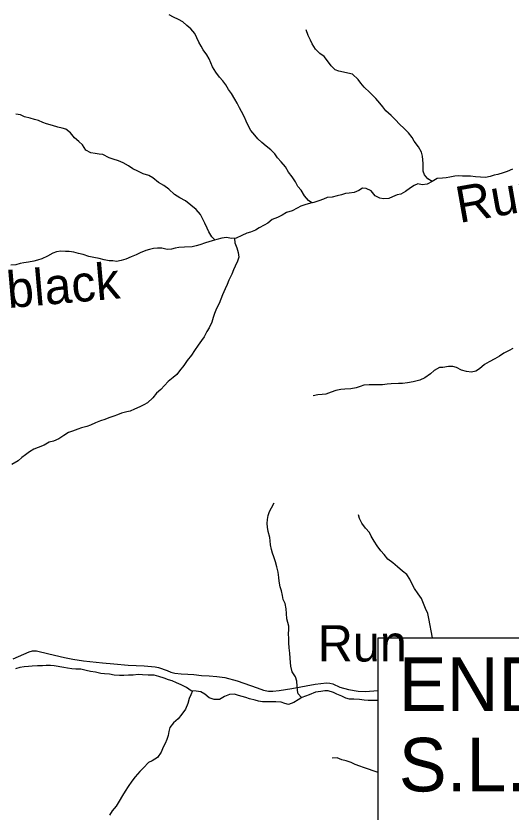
# Model space of a CAD drawing. Extents: x 0 to 34, y 0 to 22.
# Drawn here: x 4.768 to 6.061, y 15.178 to 17.257 of the extents above; entities that cross this region are included whole.
import ezdxf

# ---------------------------------------------------------------- set-up
doc = ezdxf.new("R2010")
doc.units = 0
for name, color, linetype in [('GM_X_Minor_River', 7, 'Continuous'), ('GM_X_Minor_River_Text', 7, 'Continuous'), ('GM_X_Township_Road', 7, 'Continuous'), ('SH_Text', 7, 'Continuous')]:
    doc.layers.add(name, color=color, linetype=linetype)

msp = doc.modelspace()

# ---------------------------------------------------------------- linework, layer by layer
at = {"layer": 'GM_X_Minor_River'}
for points in [[(5.5411, 16.7688), (5.5324, 16.7752), (5.5218, 16.7874), (5.5128, 16.8019), (5.5041, 16.8118), (5.4981, 16.824), (5.4894, 16.8373), (5.4804, 16.8488), (5.4721, 16.8633), (5.4612, 16.8762), (5.4517, 16.8862), (5.4446, 16.8972), (5.434, 16.9071), (5.4215, 16.9171), (5.4102, 16.927), (5.4, 16.9358), (5.3924, 16.9454), (5.3818, 16.9579), (5.3766, 16.9678), (5.3698, 16.9823), (5.365, 16.993), (5.3578, 17.0078), (5.3526, 17.0173), (5.3458, 17.0295), (5.3398, 17.0398), (5.3311, 17.0543), (5.3236, 17.0654), (5.3161, 17.0768), (5.3085, 17.0875), (5.2998, 17.097), (5.2908, 17.11), (5.2818, 17.1245), (5.2776, 17.1344), (5.2732, 17.145), (5.2671, 17.1553), (5.2577, 17.1683), (5.2521, 17.1785), (5.2464, 17.1885), (5.2412, 17.1999), (5.2356, 17.2109), (5.225, 17.2239), (5.2144, 17.2323), (5.2046, 17.2415), (5.1928, 17.248), (5.1799, 17.2538), (5.1682, 17.2599)], [(5.855, 16.8244), (5.8441, 16.8315), (5.835, 16.8422), (5.832, 16.8521), (5.8317, 16.8616), (5.8318, 16.8718), (5.8304, 16.8908), (5.8274, 16.9011), (5.8199, 16.9152), (5.8086, 16.9297), (5.8029, 16.9396), (5.7939, 16.9522), (5.7825, 16.9629), (5.7701, 16.9747), (5.7599, 16.9862), (5.7485, 16.9973), (5.7345, 17.0095), (5.7266, 17.0194), (5.7187, 17.0297), (5.7078, 17.0419), (5.6923, 17.0576), (5.6779, 17.0713), (5.6689, 17.0816), (5.6617, 17.0915), (5.6473, 17.1053), (5.6113, 17.1127), (5.6018, 17.1166), (5.5916, 17.1269), (5.5822, 17.1402), (5.5731, 17.1509), (5.5618, 17.1589), (5.5504, 17.17), (5.5418, 17.1841), (5.5373, 17.194), (5.5313, 17.2062), (5.5264, 17.2207)], [(5.2886, 16.6717), (5.2798, 16.6806), (5.2719, 16.6931), (5.2674, 16.7026), (5.2614, 16.716), (5.2561, 16.7263), (5.2501, 16.7384), (5.2388, 16.7514), (5.2252, 16.7633), (5.2112, 16.7747), (5.1964, 16.7824), (5.1828, 16.7908), (5.1676, 16.8046), (5.1544, 16.8146), (5.1411, 16.8222), (5.126, 16.8341), (5.115, 16.8406), (5.1006, 16.8449), (5.087, 16.8514), (5.0733, 16.8583), (5.062, 16.866), (5.0487, 16.8733), (5.0358, 16.8786), (5.0225, 16.8833), (5.0119, 16.8868), (4.9949, 16.8952), (4.9854, 16.896), (4.9751, 16.8976), (4.9637, 16.8999), (4.9512, 16.9065), (4.9426, 16.9209), (4.9323, 16.929), (4.9214, 16.9385), (4.9108, 16.9515), (4.8987, 16.9614), (4.8892, 16.9645), (4.8775, 16.9669), (4.8638, 16.9708), (4.8486, 16.975), (4.8388, 16.9793), (4.8274, 16.9839), (4.8168, 16.9866), (4.8054, 16.9901), (4.791, 16.994), (4.7807, 16.9986), (4.7682, 17.0009)], [(6.0651, 16.8572), (6.0514, 16.8509), (6.0407, 16.8471), (6.027, 16.8434), (6.0175, 16.8412), (6.0072, 16.8382), (5.9942, 16.8356), (5.9813, 16.8361), (5.9684, 16.8373), (5.9551, 16.8385), (5.9456, 16.8389), (5.9342, 16.839), (5.9239, 16.8398), (5.9144, 16.8387), (5.9015, 16.8365), (5.892, 16.8347), (5.8821, 16.8336), (5.8688, 16.8325), (5.8554, 16.8246), (5.8425, 16.8179), (5.8291, 16.8164), (5.8181, 16.8184), (5.8086, 16.8146), (5.7987, 16.8079), (5.7853, 16.7988), (5.7739, 16.792), (5.764, 16.7902), (5.7518, 16.785), (5.7419, 16.7801), (5.7286, 16.7794), (5.7187, 16.7817), (5.7062, 16.7875), (5.696, 16.8008), (5.6831, 16.8066), (5.6736, 16.8074), (5.6641, 16.8014), (5.6515, 16.7965), (5.6389, 16.7943), (5.6294, 16.7936), (5.6184, 16.7899), (5.6073, 16.7873), (5.5944, 16.7843), (5.5811, 16.7829), (5.5716, 16.7784), (5.559, 16.7747), (5.546, 16.7698), (5.5354, 16.7676), (5.5255, 16.765), (5.5125, 16.7605), (5.5026, 16.7552), (5.4896, 16.7485), (5.4752, 16.7436), (5.4637, 16.7368), (5.4511, 16.7312), (5.4378, 16.7252), (5.4263, 16.7162), (5.4168, 16.7109), (5.4038, 16.7041), (5.3939, 16.6978), (5.3813, 16.6929), (5.371, 16.6899), (5.3585, 16.6839), (5.3436, 16.6764), (5.331, 16.6761), (5.3185, 16.6784), (5.306, 16.677), (5.293, 16.6729), (5.2804, 16.6695), (5.2637, 16.6643), (5.2488, 16.6591), (5.2389, 16.6565), (5.2283, 16.6543), (5.2085, 16.6529), (5.1941, 16.6526), (5.1845, 16.6507), (5.1743, 16.6481), (5.1636, 16.6474), (5.1496, 16.6505), (5.1378, 16.651), (5.1275, 16.6495), (5.1169, 16.6473), (5.1073, 16.6447), (5.0928, 16.6383), (5.0822, 16.6334), (5.0696, 16.6278), (5.0551, 16.6222), (5.0433, 16.6181)], [(5.3389, 16.6763), (5.3397, 16.6643), (5.3453, 16.6513), (5.3491, 16.6395), (5.3501, 16.627), (5.3474, 16.6168), (5.3409, 16.6039), (5.3362, 16.594), (5.332, 16.583), (5.3243, 16.5671), (5.3197, 16.5562), (5.315, 16.5448), (5.3077, 16.5289), (5.3034, 16.5175), (5.2992, 16.5058), (5.2919, 16.4933), (5.2873, 16.4804), (5.2838, 16.4694), (5.2799, 16.4573), (5.2726, 16.4429), (5.2668, 16.433), (5.2599, 16.4194), (5.2534, 16.4096), (5.2442, 16.3975), (5.2346, 16.3835), (5.2269, 16.3717), (5.2158, 16.357), (5.2066, 16.3441), (5.1955, 16.3305), (5.1882, 16.3207), (5.1786, 16.3128), (5.1656, 16.3022), (5.1561, 16.2924), (5.1465, 16.2818), (5.1358, 16.272), (5.1262, 16.2595), (5.1121, 16.2467), (5.1025, 16.2414), (5.0915, 16.2362), (5.0781, 16.2306), (5.0671, 16.2253), (5.0576, 16.2231), (5.0439, 16.2194), (5.034, 16.2156), (5.0237, 16.2119), (5.0107, 16.2074), (5.0008, 16.2033), (4.9894, 16.1999), (4.9764, 16.1947), (4.9631, 16.1887), (4.9536, 16.1853), (4.9398, 16.1812), (4.9303, 16.1782), (4.9162, 16.173), (4.9059, 16.1696), (4.8937, 16.1614), (4.8807, 16.1527), (4.8666, 16.1467), (4.8556, 16.1441), (4.8419, 16.1366), (4.8266, 16.1302), (4.8148, 16.1254), (4.8041, 16.119), (4.7938, 16.1107), (4.7835, 16.1043), (4.774, 16.0956), (4.7575, 16.0858)], [(5.0433, 16.6181), (5.0311, 16.6163), (5.0216, 16.6175), (5.0121, 16.6179), (4.9992, 16.6202), (4.9856, 16.6237), (4.9715, 16.6261), (4.9586, 16.6292), (4.9442, 16.6339), (4.9317, 16.6366), (4.9199, 16.6401), (4.9074, 16.6417), (4.8975, 16.6417), (4.8853, 16.6425), (4.8743, 16.6407), (4.8644, 16.6373), (4.8507, 16.6294), (4.8362, 16.6227), (4.8247, 16.6193), (4.8148, 16.6167), (4.8011, 16.6142), (4.789, 16.6123), (4.7794, 16.6105), (4.7684, 16.6075), (4.7551, 16.6061)], [(6.0656, 16.389), (6.056, 16.3838), (6.0427, 16.3762), (6.0312, 16.3691), (6.0186, 16.3616), (6.0042, 16.354), (5.9916, 16.3473), (5.9786, 16.3352), (5.969, 16.3292), (5.958, 16.327), (5.9447, 16.3289), (5.9318, 16.3317), (5.9185, 16.339), (5.909, 16.3417), (5.8976, 16.3414), (5.8836, 16.3395), (5.8741, 16.3392), (5.8603, 16.3309), (5.8508, 16.3226), (5.8363, 16.3125), (5.8229, 16.3057), (5.8058, 16.3016), (5.7909, 16.2987), (5.778, 16.2976), (5.7674, 16.2973), (5.748, 16.2963), (5.7377, 16.2956), (5.7259, 16.2941), (5.7156, 16.2938), (5.7016, 16.2935), (5.6909, 16.2935), (5.6765, 16.2929), (5.6669, 16.2891), (5.657, 16.2861), (5.6433, 16.2832), (5.627, 16.2825), (5.6167, 16.2818), (5.6038, 16.2788), (5.592, 16.2744), (5.5779, 16.2691), (5.5684, 16.2684), (5.557, 16.2673), (5.5448, 16.2648)], [(5.5141, 15.477), (5.5053, 15.4865), (5.5035, 15.496), (5.5024, 15.507), (5.5021, 15.5203), (5.498, 15.531), (5.4901, 15.5439), (5.486, 15.5595), (5.4853, 15.569), (5.4846, 15.58), (5.4839, 15.5933), (5.4817, 15.6074), (5.4807, 15.6203), (5.4808, 15.6306), (5.4805, 15.6446), (5.4813, 15.6541), (5.481, 15.6636), (5.4787, 15.6735), (5.4761, 15.683), (5.4751, 15.6963), (5.474, 15.7085), (5.4714, 15.7225), (5.4666, 15.7336), (5.4644, 15.7434), (5.4622, 15.756), (5.4588, 15.7666), (5.4562, 15.7815), (5.4551, 15.791), (5.4533, 15.805), (5.45, 15.8183), (5.4459, 15.8317), (5.4418, 15.845), (5.4388, 15.8545), (5.4355, 15.864), (5.4329, 15.8762), (5.4322, 15.886), (5.4311, 15.8955), (5.4274, 15.9111), (5.4252, 15.9218), (5.4241, 15.9313), (5.4253, 15.9423), (5.4273, 15.9525), (5.4308, 15.9628), (5.4354, 15.9726), (5.4431, 15.9855)], [(5.8565, 15.6335), (5.8468, 15.6836), (5.8438, 15.6965), (5.8382, 15.7098), (5.8329, 15.7224), (5.8273, 15.7357), (5.819, 15.7483), (5.8096, 15.7616), (5.8021, 15.7753), (5.7972, 15.7864), (5.7893, 15.7986), (5.778, 15.8074), (5.7651, 15.8184), (5.7526, 15.8292), (5.7398, 15.8387), (5.7296, 15.8505), (5.7217, 15.8605), (5.7115, 15.8738), (5.704, 15.8856), (5.6964, 15.8986), (5.6916, 15.9081), (5.6814, 15.9196), (5.6716, 15.9325), (5.6652, 15.9447), (5.663, 15.9542)], [(5.0879, 15.5371), (5.0749, 15.536), (5.0624, 15.5354), (5.0502, 15.5347), (5.0388, 15.5344), (5.0251, 15.5356), (5.013, 15.5379), (4.9993, 15.5391), (4.9898, 15.5403), (4.9758, 15.5431), (4.9632, 15.5454), (4.9522, 15.5481), (4.9382, 15.5513), (4.9245, 15.5517), (4.9143, 15.5521), (4.9029, 15.5541), (4.8934, 15.5557), (4.8683, 15.5604), (4.8588, 15.5612), (4.8474, 15.5605), (4.8375, 15.5602), (4.8246, 15.5599), (4.8109, 15.5592), (4.8014, 15.5585), (4.7896, 15.557), (4.7782, 15.5556), (4.7671, 15.5518)], [(5.7139, 15.4699), (5.6884, 15.4691), (5.6774, 15.47), (5.6653, 15.4719), (5.6508, 15.4732), (5.6394, 15.4728), (5.6299, 15.4752), (5.6197, 15.4805), (5.6068, 15.4856), (5.5973, 15.4905), (5.5841, 15.4948), (5.5746, 15.4945), (5.5647, 15.4934), (5.5506, 15.4908), (5.5342, 15.4841), (5.5247, 15.4811), (5.5152, 15.4777), (5.5052, 15.4709), (5.4938, 15.4642), (5.4801, 15.4593), (5.4706, 15.4616), (5.4611, 15.4651), (5.4474, 15.466), (5.4124, 15.4662), (5.4022, 15.4681), (5.3927, 15.4704), (5.3787, 15.4736), (5.3684, 15.477), (5.3589, 15.4798), (5.3494, 15.4828), (5.3392, 15.4856), (5.3263, 15.4853), (5.3133, 15.4796), (5.3003, 15.4725), (5.2859, 15.4718), (5.273, 15.4768), (5.2617, 15.486), (5.2514, 15.4918), (5.2389, 15.4941), (5.2264, 15.4949), (5.2135, 15.503), (5.2002, 15.5106), (5.1881, 15.516), (5.1767, 15.5207), (5.1665, 15.5238), (5.1555, 15.528), (5.1418, 15.5322), (5.1293, 15.5354), (5.1137, 15.5354), (5.0985, 15.5367), (5.0879, 15.5371)], [(5.2293, 15.4947), (5.2248, 15.4843), (5.2209, 15.4748), (5.217, 15.4616), (5.2109, 15.4472), (5.2016, 15.4336), (5.1917, 15.4215), (5.1802, 15.4109), (5.1706, 15.3988), (5.1679, 15.3889), (5.1659, 15.3783), (5.1628, 15.3673), (5.1578, 15.3571), (5.1532, 15.3473), (5.1478, 15.3344), (5.1378, 15.3204), (5.1241, 15.3117), (5.1142, 15.3072), (5.1016, 15.294), (5.092, 15.2838), (5.0801, 15.2702), (5.0713, 15.2589), (5.0613, 15.2452), (5.0533, 15.2328), (5.0471, 15.2218), (5.0383, 15.2066), (5.0298, 15.1938), (5.0199, 15.1817), (5.013, 15.1696)], [(5.7139, 15.2818), (5.6759, 15.2942), (5.6665, 15.2976), (5.6539, 15.3023), (5.6441, 15.3073), (5.6304, 15.3119), (5.6198, 15.3146), (5.6069, 15.3196), (5.5944, 15.3185)]]:
    msp.add_lwpolyline(points, dxfattribs=at)
at = {"layer": 'GM_X_Township_Road'}
msp.add_lwpolyline([(4.7609, 15.5786), (4.8026, 15.5966), (4.8119, 15.5991), (4.8218, 15.5988), (4.8544, 15.5916), (4.8951, 15.5814), (4.917, 15.5772), (4.9448, 15.5733), (4.9944, 15.5679), (5.024, 15.5656), (5.0614, 15.5621), (5.1033, 15.5602), (5.1317, 15.5578), (5.1405, 15.5558), (5.1629, 15.5477), (5.1728, 15.5436), (5.1832, 15.5406), (5.2, 15.5388), (5.2171, 15.538), (5.2329, 15.5371), (5.253, 15.535), (5.2733, 15.5339), (5.2931, 15.5325), (5.3137, 15.5295), (5.3465, 15.5211), (5.3983, 15.5026), (5.4149, 15.4968), (5.4279, 15.4937), (5.4393, 15.4935), (5.4559, 15.4958), (5.4892, 15.5006), (5.5499, 15.5117), (5.579, 15.5153), (5.5881, 15.5146), (5.5963, 15.5128), (5.6138, 15.5047), (5.637, 15.4979), (5.662, 15.494), (5.6802, 15.493), (5.7139, 15.4958)], dxfattribs=at)
at = {"layer": 'SH_Text'}
msp.add_lwpolyline([(5.7139, 15.6335), (7.2097, 15.6335), (7.2097, 15.147), (5.7139, 15.147)], close=True, dxfattribs=at)

# ---------------------------------------------------------------- texts
at = {"layer": 'GM_X_Minor_River_Text'}
for s, height, rotation, p in [('Run', 0.0947, 10.002, (5.9262, 16.7162)), ('Lampblack', 0.09469, 5.0007, (4.4328, 16.4664)), ('Run', 0.09469, 0.0008, (5.5568, 15.5714))]:
    msp.add_text(s, height=height, rotation=rotation, dxfattribs=at).set_placement(p)
at = {"layer": 'SH_Text'}
for s, p in [('END PROJECT', (5.7682, 15.442)), ('S.L.M.  6.22', (5.7682, 15.232))]:
    msp.add_text(s, height=0.14, dxfattribs=at).set_placement(p)

doc.saveas('drawing.dxf')
